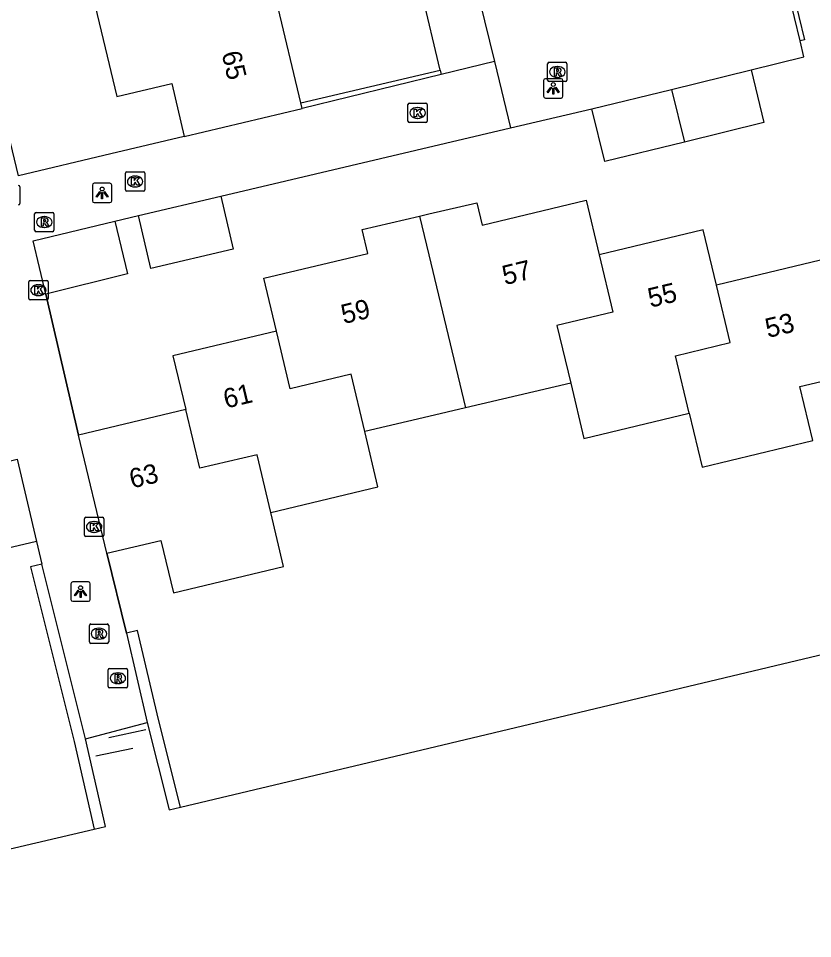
# Model space of a CAD drawing. Extents: x 158038 to 159242, y 380133 to 381214.
# Drawn here: x 158478.81 to 158519.83, y 380424.32 to 380471.82 of the extents above; entities that cross this region are included whole.
import ezdxf

# ---------------------------------------------------------------- set-up
doc = ezdxf.new("R2010")
doc.units = 0
for name, color, linetype in [('IMGEO_Brandkraan', 7, 'Continuous'), ('IMGEO_Groenvoorziening', 7, 'Continuous'), ('IMGEO_Haag', 7, 'Continuous'), ('IMGEO_Hek', 7, 'Continuous'), ('IMGEO_Kolk', 7, 'Continuous'), ('IMGEO_Lichtpunt', 7, 'Continuous'), ('IMGEO_Muur', 7, 'Continuous'), ('IMGEO_Pand', 7, 'Continuous'), ('IMGEO_Pand_nummerreeks', 7, 'Continuous'), ('IMGEO_Rioolput', 7, 'Continuous'), ('IMGEO_Voetpad_open', 7, 'Continuous')]:
    doc.layers.add(name, color=color, linetype=linetype)

msp = doc.modelspace()

# ---------------------------------------------------------------- linework, layer by layer
at = {"layer": 'IMGEO_Brandkraan'}
msp.add_line((158478.886, 380463.127), (158478.886, 380462.275), dxfattribs=at)
msp.add_lwpolyline([(158478.886, 380463.127), (158478.886, 380462.275)], dxfattribs=at)
for centre, start, end in [((158478.81, 380463.125), 1.552, 88.448), ((158478.81, 380463.125), 1.552, 88.448), ((158478.81, 380462.277), 271.552, 358.448), ((158478.81, 380462.277), 271.552, 358.448)]:
    msp.add_arc(centre, 0.0765, start, end, dxfattribs=at)
at = {"layer": 'IMGEO_Groenvoorziening'}
for points in [[(158487.178, 380431.098), (158500, 380434.154), (158563.318, 380449.24), (158565.868, 380438.275), (158590.829, 380444.121)], [(158397.967, 380442.247), (158417.202, 380429.168), (158455.352, 380438.312), (158458.616, 380424.32), (158482.724, 380429.975)]]:
    msp.add_lwpolyline(points, dxfattribs=at)
at = {"layer": 'IMGEO_Haag'}
for points in [[(158480.026, 380443.654), (158479.444, 380443.509), (158481.685, 380434.489), (158482.724, 380429.975)], [(158487.178, 380431.098), (158486.05, 380435.622), (158484.971, 380440.228), (158484.387, 380440.091)], [(158485.467, 380435.481), (158486.594, 380430.959), (158487.178, 380431.098)], [(158482.724, 380429.975), (158483.308, 380430.112), (158482.269, 380434.629)]]:
    msp.add_lwpolyline(points, dxfattribs=at)
at = {"layer": 'IMGEO_Hek'}
for points in [[(158487.377, 380465.731), (158483.582, 380464.838)], [(158483.481, 380434.696), (158485.388, 380435.112)], [(158484.724, 380434.128), (158482.818, 380433.741)]]:
    msp.add_lwpolyline(points, dxfattribs=at)
at = {"layer": 'IMGEO_Kolk'}
for p, q in [((158498.927, 380466.517), (158498.927, 380467.369)), ((158499.002, 380467.443), (158499.854, 380467.443)), ((158499.928, 380467.369), (158499.928, 380466.517)), ((158499.415, 380467.223), (158499.44, 380467.223)), ((158499.854, 380466.443), (158499.002, 380466.443)), ((158499.438, 380466.663), (158499.413, 380466.663)), ((158484.338, 380462.979), (158484.338, 380463.831)), ((158484.413, 380463.905), (158485.265, 380463.905)), ((158484.826, 380463.685), (158484.851, 380463.685)), ((158485.339, 380463.831), (158485.339, 380462.979)), ((158484.849, 380463.125), (158484.824, 380463.125)), ((158485.265, 380462.905), (158484.413, 380462.905)), ((158479.422, 380458.291), (158480.274, 380458.291)), ((158479.347, 380457.365), (158479.347, 380458.217)), ((158479.835, 380458.071), (158479.86, 380458.071)), ((158480.348, 380458.217), (158480.348, 380457.365)), ((158479.858, 380457.511), (158479.833, 380457.511)), ((158480.274, 380457.291), (158479.422, 380457.291)), ((158482.223, 380445.145), (158482.223, 380445.997)), ((158482.298, 380446.071), (158483.15, 380446.071)), ((158483.224, 380445.997), (158483.224, 380445.145)), ((158482.711, 380445.851), (158482.736, 380445.851)), ((158483.15, 380445.071), (158482.298, 380445.071)), ((158482.734, 380445.291), (158482.709, 380445.291))]:
    msp.add_line(p, q, dxfattribs=at)
for points in [[(158498.927, 380466.517), (158498.927, 380467.369)], [(158499.002, 380467.443), (158499.854, 380467.443)], [(158499.928, 380467.369), (158499.928, 380466.517)], [(158499.248, 380467.143), (158499.371, 380467.143), (158499.371, 380466.992), (158499.501, 380467.143), (158499.665, 380467.143), (158499.519, 380466.992), (158499.672, 380466.743), (158499.52, 380466.743), (158499.435, 380466.907), (158499.371, 380466.84), (158499.371, 380466.743), (158499.248, 380466.743), (158499.248, 380467.143)], [(158499.854, 380466.443), (158499.002, 380466.443)], [(158484.338, 380462.979), (158484.338, 380463.831)], [(158484.413, 380463.905), (158485.265, 380463.905)], [(158484.659, 380463.605), (158484.782, 380463.605), (158484.782, 380463.454), (158484.912, 380463.605), (158485.076, 380463.605), (158484.93, 380463.454), (158485.083, 380463.205), (158484.931, 380463.205), (158484.846, 380463.369), (158484.782, 380463.302), (158484.782, 380463.205), (158484.659, 380463.205), (158484.659, 380463.605)], [(158485.339, 380463.831), (158485.339, 380462.979)], [(158485.265, 380462.905), (158484.413, 380462.905)], [(158479.422, 380458.291), (158480.274, 380458.291)], [(158479.347, 380457.365), (158479.347, 380458.217)], [(158479.668, 380457.991), (158479.791, 380457.991), (158479.791, 380457.84), (158479.921, 380457.991), (158480.085, 380457.991), (158479.939, 380457.84), (158480.092, 380457.591), (158479.94, 380457.591), (158479.855, 380457.755), (158479.791, 380457.688), (158479.791, 380457.591), (158479.668, 380457.591), (158479.668, 380457.991)], [(158480.348, 380458.217), (158480.348, 380457.365)], [(158480.274, 380457.291), (158479.422, 380457.291)], [(158482.223, 380445.145), (158482.223, 380445.997)], [(158482.298, 380446.071), (158483.15, 380446.071)], [(158483.224, 380445.997), (158483.224, 380445.145)], [(158482.544, 380445.771), (158482.667, 380445.771), (158482.667, 380445.62), (158482.797, 380445.771), (158482.961, 380445.771), (158482.815, 380445.62), (158482.968, 380445.371), (158482.816, 380445.371), (158482.731, 380445.535), (158482.667, 380445.468), (158482.667, 380445.371), (158482.544, 380445.371), (158482.544, 380445.771)], [(158483.15, 380445.071), (158482.298, 380445.071)]]:
    msp.add_lwpolyline(points, dxfattribs=at)
for centre, start, end in [((158499.004, 380467.367), 91.552, 178.448), ((158499.004, 380467.367), 91.552, 178.448), ((158499.852, 380467.367), 1.552, 88.448), ((158499.852, 380467.367), 1.552, 88.448), ((158499.004, 380466.519), 181.552, 268.448), ((158499.004, 380466.519), 181.552, 268.448), ((158499.852, 380466.519), 271.552, 358.448), ((158499.852, 380466.519), 271.552, 358.448), ((158484.415, 380463.829), 91.552, 178.448), ((158484.415, 380463.829), 91.552, 178.448), ((158485.263, 380463.829), 1.552, 88.448), ((158485.263, 380463.829), 1.552, 88.448), ((158484.415, 380462.981), 181.552, 268.448), ((158484.415, 380462.981), 181.552, 268.448), ((158485.263, 380462.981), 271.552, 358.448), ((158485.263, 380462.981), 271.552, 358.448), ((158479.424, 380458.215), 91.552, 178.448), ((158479.424, 380458.215), 91.552, 178.448), ((158480.272, 380458.215), 1.552, 88.448), ((158480.272, 380458.215), 1.552, 88.448), ((158479.424, 380457.367), 181.552, 268.448), ((158479.424, 380457.367), 181.552, 268.448), ((158480.272, 380457.367), 271.552, 358.448), ((158480.272, 380457.367), 271.552, 358.448), ((158482.3, 380445.995), 91.552, 178.448), ((158482.3, 380445.995), 91.552, 178.448), ((158483.148, 380445.995), 1.552, 88.448), ((158483.148, 380445.995), 1.552, 88.448), ((158482.3, 380445.147), 181.552, 268.448), ((158482.3, 380445.147), 181.552, 268.448), ((158483.148, 380445.147), 271.552, 358.448), ((158483.148, 380445.147), 271.552, 358.448)]:
    msp.add_arc(centre, 0.0765, start, end, dxfattribs=at)
for centre, major_axis, ratio, start_param, end_param in [((158499.414, 380466.943), (-0.387, 0.002), 0.722429, 4.712389, 7.853982), ((158499.439, 380466.943), (-0.39, 0.002), 0.717154, 1.570796, 4.712389), ((158484.825, 380463.405), (-0.387, 0.002), 0.722429, 4.712389, 7.853982), ((158484.85, 380463.405), (-0.39, 0.002), 0.717154, 1.570796, 4.712389), ((158479.834, 380457.791), (-0.387, 0.002), 0.722429, 4.712389, 7.853982), ((158479.859, 380457.791), (-0.39, 0.002), 0.717154, 1.570796, 4.712389), ((158482.71, 380445.571), (-0.387, 0.002), 0.722429, 4.712389, 7.853982), ((158482.735, 380445.571), (-0.39, 0.002), 0.717154, 1.570796, 4.712389)]:
    msp.add_ellipse(centre, major_axis=major_axis, ratio=ratio, start_param=start_param, end_param=end_param, dxfattribs=at)
at = {"layer": 'IMGEO_Lichtpunt'}
for p, q in [((158506.837, 380468.708), (158506.029, 380468.708)), ((158506.837, 380468.708), (158506.029, 380468.708)), ((158505.935, 380468.613), (158505.935, 380467.806)), ((158505.935, 380468.613), (158505.935, 380467.806)), ((158506.931, 380467.806), (158506.931, 380468.613)), ((158506.931, 380467.806), (158506.931, 380468.613)), ((158506.029, 380467.712), (158506.837, 380467.712)), ((158506.029, 380467.712), (158506.837, 380467.712)), ((158482.636, 380463.217), (158482.636, 380462.41)), ((158482.636, 380463.217), (158482.636, 380462.41)), ((158483.538, 380463.312), (158482.73, 380463.312)), ((158483.538, 380463.312), (158482.73, 380463.312)), ((158483.632, 380462.41), (158483.632, 380463.217)), ((158483.632, 380462.41), (158483.632, 380463.217)), ((158482.73, 380462.316), (158483.538, 380462.316)), ((158482.73, 380462.316), (158483.538, 380462.316)), ((158481.524, 380442.636), (158481.524, 380441.829)), ((158481.524, 380442.636), (158481.524, 380441.829)), ((158482.426, 380442.731), (158481.618, 380442.731)), ((158482.426, 380442.731), (158481.618, 380442.731)), ((158482.52, 380441.829), (158482.52, 380442.636)), ((158482.52, 380441.829), (158482.52, 380442.636)), ((158481.618, 380441.735), (158482.426, 380441.735)), ((158481.618, 380441.735), (158482.426, 380441.735))]:
    msp.add_line(p, q, dxfattribs=at)
for points in [[(158506.309, 380468.277), (158506.348, 380468.249), (158506.16, 380467.987), (158506.122, 380468.014), (158506.309, 380468.277)], [(158506.411, 380468.229), (158506.458, 380468.229), (158506.458, 380467.907), (158506.411, 380467.907), (158506.411, 380468.229)], [(158506.521, 380468.249), (158506.559, 380468.276), (158506.746, 380468.014), (158506.707, 380467.986), (158506.521, 380468.249)], [(158483.01, 380462.881), (158483.049, 380462.853), (158482.861, 380462.591), (158482.823, 380462.618), (158483.01, 380462.881)], [(158483.112, 380462.833), (158483.159, 380462.833), (158483.159, 380462.511), (158483.112, 380462.511), (158483.112, 380462.833)], [(158483.222, 380462.853), (158483.26, 380462.88), (158483.447, 380462.618), (158483.408, 380462.59), (158483.222, 380462.853)], [(158481.898, 380442.3), (158481.937, 380442.272), (158481.749, 380442.01), (158481.711, 380442.037), (158481.898, 380442.3)], [(158482, 380442.252), (158482.047, 380442.252), (158482.047, 380441.93), (158482, 380441.93), (158482, 380442.252)], [(158482.11, 380442.272), (158482.148, 380442.299), (158482.335, 380442.037), (158482.296, 380442.009), (158482.11, 380442.272)]]:
    msp.add_lwpolyline(points, dxfattribs=at)
for centre in [(158506.434, 380468.411), (158483.135, 380463.015), (158482.023, 380442.434)]:
    msp.add_circle(centre, 0.0994, dxfattribs=at)
for centre, start, end in [((158506.029, 380468.613), 90, 180), ((158506.029, 380468.613), 90, 180), ((158506.837, 380468.613), 0, 90), ((158506.837, 380468.613), 0, 90), ((158506.029, 380467.806), 180, 270), ((158506.029, 380467.806), 180, 270), ((158506.837, 380467.806), 270, 0), ((158506.837, 380467.806), 270, 360), ((158482.73, 380463.217), 90, 180), ((158482.73, 380463.217), 90, 180), ((158483.538, 380463.217), 0, 90), ((158483.538, 380463.217), 0, 90), ((158482.73, 380462.41), 180, 270), ((158482.73, 380462.41), 180, 270), ((158483.538, 380462.41), 270, 0), ((158483.538, 380462.41), 270, 360), ((158481.618, 380442.636), 90, 180), ((158481.618, 380442.636), 90, 180), ((158482.426, 380442.636), 0, 90), ((158482.426, 380442.636), 0, 90), ((158481.618, 380441.829), 180, 270), ((158481.618, 380441.829), 180, 270), ((158482.426, 380441.829), 270, 0), ((158482.426, 380441.829), 270, 360)]:
    msp.add_arc(centre, 0.0946, start, end, dxfattribs=at)
at = {"layer": 'IMGEO_Muur'}
for points in [[(158519.177, 380470.658), (158518.596, 380473.09)], [(158518.829, 380473.147), (158519.41, 380470.714), (158519.177, 380470.658)], [(158493.394, 380467.458), (158500.592, 380469.158)], [(158500.647, 380468.924), (158493.461, 380467.176)], [(158480.225, 380457.593), (158481.92, 380450.302)], [(158483.377, 380444.21), (158484.387, 380440.091)]]:
    msp.add_lwpolyline(points, dxfattribs=at)
at = {"layer": 'IMGEO_Pand'}
for points in [[(158485.426, 380474.398), (158482.489, 380473.699), (158483.902, 380467.788), (158486.729, 380468.459), (158487.377, 380465.731)], [(158500.592, 380469.158), (158499.645, 380473.156), (158502.365, 380473.819)], [(158502.365, 380473.819), (158503.394, 380469.601)], [(158493.394, 380467.458), (158492.142, 380472.726)], [(158503.394, 380469.601), (158500.647, 380468.924)], [(158500.592, 380469.158), (158500.647, 380468.924)], [(158512.537, 380468.159), (158516.651, 380469.164)], [(158516.651, 380469.164), (158517.315, 380466.444), (158513.202, 380465.439)], [(158508.423, 380467.154), (158512.537, 380468.159)], [(158512.537, 380468.159), (158513.202, 380465.439)], [(158493.461, 380467.176), (158493.394, 380467.458)], [(158487.377, 380465.731), (158493.461, 380467.176)], [(158513.202, 380465.439), (158509.088, 380464.434), (158508.423, 380467.154)], [(158485.01, 380461.644), (158489.266, 380462.642)], [(158489.266, 380462.642), (158489.905, 380459.915), (158485.649, 380458.918), (158485.01, 380461.644)], [(158499.52, 380461.614), (158500, 380461.725), (158502.486, 380462.301), (158502.762, 380461.149), (158508.125, 380462.435), (158508.8, 380459.623)], [(158492.137, 380455.67), (158491.484, 380458.418), (158496.851, 380459.693), (158496.557, 380460.928), (158499.52, 380461.614)], [(158499.52, 380461.614), (158500, 380459.612), (158501.893, 380451.715)], [(158480.225, 380457.593), (158479.572, 380460.347), (158483.797, 380461.356)], [(158483.797, 380461.356), (158484.447, 380458.632), (158480.225, 380457.593)], [(158514.863, 380458.059), (158514.179, 380460.913), (158508.8, 380459.623)], [(158508.8, 380459.623), (158509.511, 380456.655), (158506.62, 380455.961), (158507.332, 380452.994)], [(158520.24, 380459.349), (158514.863, 380458.059)], [(158513.456, 380451.438), (158512.743, 380454.409), (158515.576, 380455.088), (158514.863, 380458.059)], [(158492.137, 380455.67), (158486.794, 380454.401), (158487.453, 380451.625)], [(158496.701, 380450.495), (158495.998, 380453.453), (158492.85, 380452.705), (158492.137, 380455.67)], [(158513.456, 380451.438), (158514.122, 380448.661), (158519.832, 380450.031), (158519.165, 380452.814), (158521.663, 380453.413)], [(158507.332, 380452.994), (158501.893, 380451.715)], [(158507.332, 380452.994), (158508.018, 380450.134), (158513.456, 380451.438)], [(158487.453, 380451.625), (158481.92, 380450.302)], [(158491.841, 380446.318), (158491.134, 380449.298), (158488.181, 380448.598), (158487.453, 380451.625)], [(158501.893, 380451.715), (158500, 380451.27), (158496.701, 380450.495)], [(158483.377, 380444.21), (158481.92, 380450.302)], [(158491.841, 380446.318), (158497.381, 380447.633), (158496.701, 380450.495)], [(158477.365, 380448.728), (158478.743, 380449.061), (158479.747, 380444.82)], [(158479.747, 380444.82), (158477.022, 380444.175), (158476.021, 380448.403), (158477.365, 380448.728)], [(158483.377, 380444.21), (158486.17, 380444.878), (158486.813, 380442.171), (158492.504, 380443.523), (158491.841, 380446.318)]]:
    msp.add_lwpolyline(points, dxfattribs=at)
at = {"layer": 'IMGEO_Rioolput'}
for p, q in [((158506.139, 380468.632), (158506.139, 380469.484)), ((158506.214, 380469.558), (158507.066, 380469.558)), ((158506.627, 380469.338), (158506.652, 380469.338)), ((158507.14, 380469.484), (158507.14, 380468.632)), ((158506.65, 380468.778), (158506.625, 380468.778)), ((158507.066, 380468.558), (158506.214, 380468.558)), ((158479.649, 380460.883), (158479.649, 380461.735)), ((158479.724, 380461.809), (158480.576, 380461.809)), ((158480.137, 380461.589), (158480.162, 380461.589)), ((158480.65, 380461.735), (158480.65, 380460.883)), ((158480.576, 380460.809), (158479.724, 380460.809)), ((158480.16, 380461.029), (158480.135, 380461.029)), ((158482.477, 380439.634), (158482.477, 380440.486)), ((158482.552, 380440.56), (158483.404, 380440.56)), ((158482.965, 380440.34), (158482.99, 380440.34)), ((158483.478, 380440.486), (158483.478, 380439.634)), ((158482.988, 380439.78), (158482.963, 380439.78)), ((158483.404, 380439.56), (158482.552, 380439.56)), ((158483.449, 380437.334), (158483.449, 380438.186)), ((158483.524, 380438.26), (158484.376, 380438.26)), ((158483.937, 380438.04), (158483.962, 380438.04)), ((158484.45, 380438.186), (158484.45, 380437.334)), ((158483.96, 380437.48), (158483.935, 380437.48)), ((158484.376, 380437.26), (158483.524, 380437.26))]:
    msp.add_line(p, q, dxfattribs=at)
for points in [[(158506.139, 380468.632), (158506.139, 380469.484)], [(158506.214, 380469.558), (158507.066, 380469.558)], [(158506.728, 380469.256), (158506.476, 380469.258), (158506.476, 380468.858)], [(158506.654, 380469.177), (158506.6, 380469.177), (158506.6, 380469.096)], [(158507.14, 380469.484), (158507.14, 380468.632)], [(158506.476, 380468.858), (158506.6, 380468.858), (158506.6, 380469.02), (158506.611, 380469.02)], [(158506.6, 380469.096), (158506.652, 380469.096)], [(158506.658, 380468.991), (158506.729, 380468.858), (158506.869, 380468.858), (158506.804, 380468.984)], [(158507.066, 380468.558), (158506.214, 380468.558)], [(158479.649, 380460.883), (158479.649, 380461.735)], [(158479.724, 380461.809), (158480.576, 380461.809)], [(158480.65, 380461.735), (158480.65, 380460.883)], [(158480.238, 380461.507), (158479.986, 380461.509), (158479.986, 380461.109)], [(158479.986, 380461.109), (158480.11, 380461.109), (158480.11, 380461.271), (158480.121, 380461.271)], [(158480.164, 380461.428), (158480.11, 380461.428), (158480.11, 380461.347)], [(158480.11, 380461.347), (158480.162, 380461.347)], [(158480.168, 380461.242), (158480.239, 380461.109), (158480.379, 380461.109), (158480.314, 380461.235)], [(158480.576, 380460.809), (158479.724, 380460.809)], [(158482.477, 380439.634), (158482.477, 380440.486)], [(158482.552, 380440.56), (158483.404, 380440.56)], [(158483.066, 380440.258), (158482.814, 380440.26), (158482.814, 380439.86)], [(158483.478, 380440.486), (158483.478, 380439.634)], [(158482.814, 380439.86), (158482.938, 380439.86), (158482.938, 380440.022), (158482.949, 380440.022)], [(158482.992, 380440.179), (158482.938, 380440.179), (158482.938, 380440.098)], [(158482.938, 380440.098), (158482.99, 380440.098)], [(158482.996, 380439.993), (158483.067, 380439.86), (158483.207, 380439.86), (158483.142, 380439.986)], [(158483.404, 380439.56), (158482.552, 380439.56)], [(158483.449, 380437.334), (158483.449, 380438.186)], [(158483.524, 380438.26), (158484.376, 380438.26)], [(158484.038, 380437.958), (158483.786, 380437.96), (158483.786, 380437.56)], [(158483.964, 380437.879), (158483.91, 380437.879), (158483.91, 380437.798)], [(158484.45, 380438.186), (158484.45, 380437.334)], [(158483.786, 380437.56), (158483.91, 380437.56), (158483.91, 380437.722), (158483.921, 380437.722)], [(158483.91, 380437.798), (158483.962, 380437.798)], [(158483.968, 380437.693), (158484.039, 380437.56), (158484.179, 380437.56), (158484.114, 380437.686)], [(158484.376, 380437.26), (158483.524, 380437.26)]]:
    msp.add_lwpolyline(points, dxfattribs=at)
for centre, radius, start, end in [((158506.216, 380469.482), 0.0765, 91.552, 178.448), ((158506.216, 380469.482), 0.0765, 91.552, 178.448), ((158506.66, 380469.081), 0.0964, 77.0061, 93.1865), ((158506.674, 380469.138), 0.0378, 276.6634, 79.6772), ((158506.727, 380469.146), 0.109, 350.3612, 89.416), ((158507.064, 380469.482), 0.0765, 1.552, 88.448), ((158507.064, 380469.482), 0.0765, 1.552, 88.448), ((158506.61, 380468.967), 0.0533, 26.0293, 88.6989), ((158506.636, 380469.285), 0.19, 274.7715, 282.9687), ((158506.725, 380469.146), 0.112, 277.5842, 350.9817), ((158506.709, 380468.931), 0.108, 29.5134, 73.7905), ((158506.216, 380468.634), 0.0765, 181.552, 268.448), ((158506.216, 380468.634), 0.0765, 181.552, 268.448), ((158507.064, 380468.634), 0.0765, 271.552, 358.448), ((158507.064, 380468.634), 0.0765, 271.552, 358.448), ((158479.726, 380461.733), 0.0765, 91.552, 178.448), ((158479.726, 380461.733), 0.0765, 91.552, 178.448), ((158480.574, 380461.733), 0.0765, 1.552, 88.448), ((158480.574, 380461.733), 0.0765, 1.552, 88.448), ((158480.12, 380461.218), 0.0533, 26.0293, 88.6989), ((158480.146, 380461.536), 0.19, 274.7715, 282.9687), ((158480.17, 380461.332), 0.0964, 77.0061, 93.1865), ((158480.184, 380461.389), 0.0378, 276.6634, 79.6772), ((158480.237, 380461.397), 0.109, 350.3612, 89.416), ((158480.235, 380461.397), 0.112, 277.5842, 350.9817), ((158480.219, 380461.182), 0.108, 29.5134, 73.7905), ((158479.726, 380460.885), 0.0765, 181.552, 268.448), ((158479.726, 380460.885), 0.0765, 181.552, 268.448), ((158480.574, 380460.885), 0.0765, 271.552, 358.448), ((158480.574, 380460.885), 0.0765, 271.552, 358.448), ((158482.554, 380440.484), 0.0765, 91.552, 178.448), ((158482.554, 380440.484), 0.0765, 91.552, 178.448), ((158483.065, 380440.148), 0.109, 350.3612, 89.416), ((158483.402, 380440.484), 0.0765, 1.552, 88.448), ((158483.402, 380440.484), 0.0765, 1.552, 88.448), ((158482.948, 380439.969), 0.0533, 26.0293, 88.6989), ((158482.974, 380440.287), 0.19, 274.7715, 282.9687), ((158482.998, 380440.083), 0.0964, 77.0061, 93.1865), ((158483.012, 380440.14), 0.0378, 276.6634, 79.6772), ((158483.063, 380440.148), 0.112, 277.5842, 350.9817), ((158483.047, 380439.933), 0.108, 29.5134, 73.7905), ((158482.554, 380439.636), 0.0765, 181.552, 268.448), ((158482.554, 380439.636), 0.0765, 181.552, 268.448), ((158483.402, 380439.636), 0.0765, 271.552, 358.448), ((158483.402, 380439.636), 0.0765, 271.552, 358.448), ((158483.526, 380438.184), 0.0765, 91.552, 178.448), ((158483.526, 380438.184), 0.0765, 91.552, 178.448), ((158483.97, 380437.783), 0.0964, 77.0061, 93.1865), ((158483.984, 380437.84), 0.0378, 276.6634, 79.6772), ((158484.037, 380437.848), 0.109, 350.3612, 89.416), ((158484.035, 380437.848), 0.112, 277.5842, 350.9817), ((158484.374, 380438.184), 0.0765, 1.552, 88.448), ((158484.374, 380438.184), 0.0765, 1.552, 88.448), ((158483.92, 380437.669), 0.0533, 26.0293, 88.6989), ((158483.946, 380437.987), 0.19, 274.7715, 282.9687), ((158484.019, 380437.633), 0.108, 29.5134, 73.7905), ((158483.526, 380437.336), 0.0765, 181.552, 268.448), ((158483.526, 380437.336), 0.0765, 181.552, 268.448), ((158484.374, 380437.336), 0.0765, 271.552, 358.448), ((158484.374, 380437.336), 0.0765, 271.552, 358.448)]:
    msp.add_arc(centre, radius, start, end, dxfattribs=at)
for centre, major_axis, ratio, start_param, end_param in [((158506.626, 380469.058), (-0.387, 0.002), 0.722429, 4.712389, 7.853982), ((158506.651, 380469.058), (-0.39, 0.002), 0.717154, 1.570796, 4.712389), ((158480.136, 380461.309), (-0.387, 0.002), 0.722429, 4.712389, 7.853982), ((158480.161, 380461.309), (-0.39, 0.002), 0.717154, 1.570796, 4.712389), ((158482.964, 380440.06), (-0.387, 0.002), 0.722429, 4.712389, 7.853982), ((158482.989, 380440.06), (-0.39, 0.002), 0.717154, 1.570796, 4.712389), ((158483.936, 380437.76), (-0.387, 0.002), 0.722429, 4.712389, 7.853982), ((158483.961, 380437.76), (-0.39, 0.002), 0.717154, 1.570796, 4.712389)]:
    msp.add_ellipse(centre, major_axis=major_axis, ratio=ratio, start_param=start_param, end_param=end_param, dxfattribs=at)
at = {"layer": 'IMGEO_Voetpad_open'}
for points in [[(158487.377, 380465.731), (158483.582, 380464.838), (158478.812, 380463.703), (158477.163, 380470.503), (158475.391, 380477.812), (158471.558, 380476.943), (158466.926, 380475.805), (158421.248, 380464.932), (158415.825, 380468.607)], [(158516.651, 380469.164), (158519.373, 380469.833), (158519.177, 380470.658)], [(158503.394, 380469.601), (158504.232, 380466.166)], [(158504.232, 380466.166), (158508.423, 380467.154)], [(158489.266, 380462.642), (158504.232, 380466.166)], [(158483.797, 380461.356), (158485.01, 380461.644)], [(158481.92, 380450.302), (158480.225, 380457.593)], [(158479.747, 380444.82), (158480.026, 380443.654)], [(158484.387, 380440.091), (158483.377, 380444.21)], [(158482.269, 380434.629), (158480.026, 380443.654)], [(158484.387, 380440.091), (158485.467, 380435.481)], [(158482.269, 380434.629), (158485.467, 380435.481)]]:
    msp.add_lwpolyline(points, dxfattribs=at)

# ---------------------------------------------------------------- texts
at = {"layer": 'IMGEO_Pand_nummerreeks'}
for s, rotation, p in [('65', 283.3784, (158489.299, 380470.02)), ('57', 13.5711, (158503.931, 380458.049)), ('55', 13.4861, (158511.451, 380456.885)), ('59', 13.5711, (158495.611, 380456.04)), ('53', 13.4871, (158517.513, 380455.321)), ('61', 13.3606, (158489.53, 380451.679)), ('63', 13.361, (158484.674, 380447.551))]:
    msp.add_text(s, height=1, rotation=rotation, dxfattribs=at).set_placement(p)

doc.saveas('drawing.dxf')
